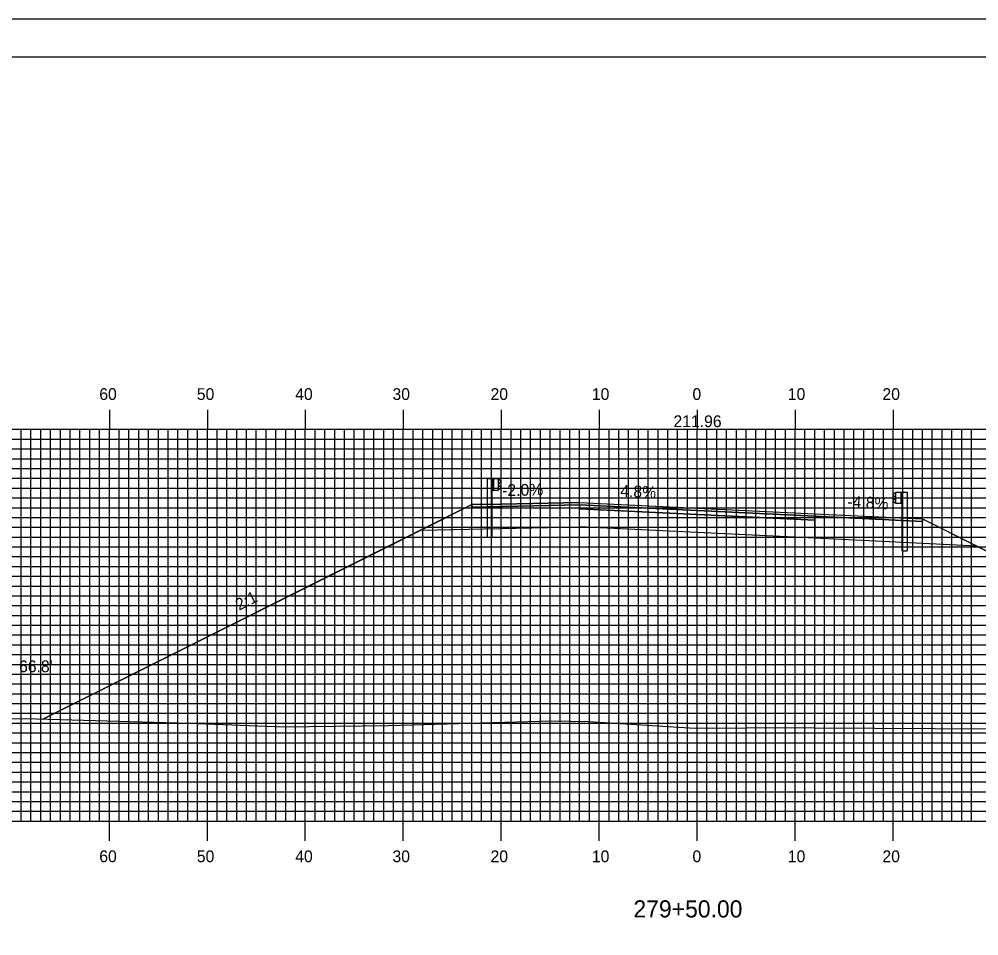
# Model space of a CAD drawing. Extents: x 1810587 to 1810930, y 442591 to 442811.
# Drawn here: x 1810683.2 to 1810781.1, y 442716.9 to 442810.5 of the extents above; entities that cross this region are included whole.
import ezdxf

# ---------------------------------------------------------------- set-up
doc = ezdxf.new("R2010")
doc.units = 0
for name, color, linetype in [('ANNOTATION', 7, 'Continuous'), ('BORDER', 7, 'Continuous'), ('D_Guardrail_Beam_Lt', 7, 'Continuous'), ('D_Guardrail_Beam_Rt', 7, 'Continuous'), ('D_Roadway_Centerline', 7, 'Continuous'), ('D_Roadway_Centerline_Text', 7, 'Continuous'), ('D_Roadway_Edge_Shoulder', 7, 'Continuous'), ('D_Roadway_Edge_TW', 7, 'Continuous'), ('D_Roadway_Pavement', 7, 'Continuous'), ('D_Roadway_SlopeLines', 7, 'Continuous'), ('D_Roadway_SubGrade', 7, 'Continuous'), ('D_Text_Standard', 7, 'Continuous'), ('H_V ANNOTATION', 7, 'Continuous'), ('MAJOR', 7, 'Continuous'), ('MINOR', 7, 'Continuous'), ('PLOT BOUNDARY', 7, 'Continuous'), ('S_Roadway_Centerline', 7, 'Continuous')]:
    doc.layers.add(name, color=color, linetype=linetype)

msp = doc.modelspace()

# ---------------------------------------------------------------- linework, layer by layer
at = {"layer": 'BORDER'}
msp.add_lwpolyline([(1810602.777, 442596.665), (1810922.777, 442596.665), (1810922.777, 442806.665), (1810602.777, 442806.665)], close=True, dxfattribs=at)
at = {"layer": 'D_Guardrail_Beam_Lt'}
for p, q in [((1810730.947, 442763.62), (1810730.947, 442757.62)), ((1810731.418, 442763.62), (1810730.947, 442763.62)), ((1810732.106, 442763.62), (1810731.418, 442763.62)), ((1810731.418, 442763.62), (1810731.418, 442762.453)), ((1810731.481, 442763.62), (1810731.481, 442762.453)), ((1810731.585, 442763.62), (1810731.585, 442762.453)), ((1810732.106, 442762.453), (1810732.106, 442763.62)), ((1810732.106, 442763.536), (1810732.18, 442763.522)), ((1810732.339, 442763.272), (1810732.144, 442763.136)), ((1810732.196, 442763.515), (1810732.339, 442763.415)), ((1810731.418, 442762.453), (1810732.106, 442762.453)), ((1810731.439, 442757.62), (1810731.439, 442762.453)), ((1810732.18, 442762.551), (1810732.106, 442762.536)), ((1810732.11, 442763.071), (1810732.11, 442763.001)), ((1810732.144, 442762.937), (1810732.339, 442762.801)), ((1810732.339, 442762.657), (1810732.196, 442762.557)), ((1810731.439, 442757.62), (1810730.947, 442757.62))]:
    msp.add_line(p, q, dxfattribs=at)
for centre, major_axis, start_param, end_param in [((1810732.189, 442763.071), (-0.0789, 0), 5.323254, 6.283185), ((1810732.172, 442763.481), (0.0417, 0), 0.959931, 1.376053), ((1810732.289, 442763.343), (0.0877, 0), 5.323254, 7.243116), ((1810732.189, 442763.001), (-0.0789, 0), 6.283185, 7.243116), ((1810732.172, 442762.591), (0.0417, 0), 4.907132, 5.323254), ((1810732.289, 442762.729), (0.0877, 0), 5.323254, 7.243116)]:
    msp.add_ellipse(centre, major_axis=major_axis, ratio=0.995501, start_param=start_param, end_param=end_param, dxfattribs=at)
at = {"layer": 'D_Guardrail_Beam_Rt'}
for p, q in [((1810772.647, 442762.16), (1810772.573, 442762.146)), ((1810772.647, 442762.244), (1810773.335, 442762.244)), ((1810772.647, 442761.077), (1810772.647, 442762.244)), ((1810773.168, 442762.244), (1810773.168, 442761.077)), ((1810773.272, 442762.244), (1810773.272, 442761.077)), ((1810773.335, 442762.244), (1810773.806, 442762.244)), ((1810773.335, 442762.244), (1810773.335, 442761.077)), ((1810773.806, 442762.244), (1810773.806, 442756.244)), ((1810772.557, 442762.139), (1810772.414, 442762.039)), ((1810772.414, 442761.896), (1810772.609, 442761.76)), ((1810772.609, 442761.561), (1810772.414, 442761.425)), ((1810772.414, 442761.281), (1810772.557, 442761.181)), ((1810772.573, 442761.175), (1810772.647, 442761.16)), ((1810772.643, 442761.695), (1810772.643, 442761.625)), ((1810773.335, 442761.077), (1810772.647, 442761.077)), ((1810773.314, 442756.244), (1810773.314, 442761.077)), ((1810773.314, 442756.244), (1810773.806, 442756.244))]:
    msp.add_line(p, q, dxfattribs=at)
for centre, major_axis, start_param, end_param in [((1810772.464, 442761.967), (-0.0877, 0), 5.323254, 7.243116), ((1810772.464, 442761.353), (-0.0877, 0), 5.323254, 7.243116), ((1810772.581, 442762.105), (-0.0417, 0), 4.907132, 5.323254), ((1810772.581, 442761.215), (-0.0417, 0), 0.959931, 1.376053), ((1810772.564, 442761.695), (0.0789, 0), 0, 0.959931), ((1810772.564, 442761.625), (0.0789, 0), 5.323254, 6.283185)]:
    msp.add_ellipse(centre, major_axis=major_axis, ratio=0.995501, start_param=start_param, end_param=end_param, dxfattribs=at)
at = {"layer": 'D_Roadway_Centerline'}
msp.add_lwpolyline([(1810685.574, 442739.075), (1810724.168, 442758.372), (1810729.377, 442760.976), (1810732.377, 442761.036), (1810740.377, 442761.196), (1810752.377, 442760.62), (1810764.377, 442760.044), (1810772.377, 442759.66), (1810775.377, 442759.516), (1810780.908, 442756.751), (1810818.962, 442737.723)], dxfattribs=at)
at = {"layer": 'D_Roadway_Edge_Shoulder'}
for points in [[(1810740.377, 442761.196), (1810732.377, 442761.036), (1810732.377, 442761.036), (1810729.377, 442760.976), (1810729.377, 442760.726), (1810740.377, 442760.946)], [(1810764.377, 442760.044), (1810772.377, 442759.66), (1810772.377, 442759.66), (1810775.377, 442759.516), (1810775.377, 442759.266), (1810764.377, 442759.794)]]:
    msp.add_lwpolyline(points, close=True, dxfattribs=at)
at = {"layer": 'D_Roadway_Edge_TW'}
msp.add_lwpolyline([(1810740.377, 442760.946), (1810740.377, 442761.196), (1810752.377, 442760.62), (1810764.377, 442760.044), (1810764.377, 442759.794), (1810752.377, 442760.37)], close=True, dxfattribs=at)
at = {"layer": 'D_Roadway_Pavement'}
msp.add_lwpolyline([(1810740.377, 442760.53), (1810740.377, 442760.946), (1810752.377, 442760.37), (1810764.377, 442759.794), (1810764.377, 442759.378), (1810752.377, 442759.954)], close=True, dxfattribs=at)
for points in [[(1810740.377, 442760.946), (1810740.377, 442760.53)], [(1810764.377, 442759.794), (1810764.377, 442759.378)]]:
    msp.add_lwpolyline(points, dxfattribs=at)
at = {"layer": 'D_Roadway_SlopeLines'}
for points in [[(1810729.377, 442760.976), (1810685.574, 442739.075)], [(1810775.377, 442759.516), (1810818.962, 442737.723)]]:
    msp.add_lwpolyline(points, dxfattribs=at)
at = {"layer": 'D_Roadway_SubGrade'}
for points in [[(1810740.377, 442760.53), (1810740.377, 442760.946), (1810729.377, 442760.726), (1810729.377, 442760.976), (1810724.168, 442758.372), (1810740.377, 442758.696)], [(1810740.377, 442758.696), (1810740.377, 442760.946), (1810740.377, 442760.53), (1810752.377, 442759.954), (1810764.377, 442759.378), (1810764.377, 442759.794), (1810764.377, 442757.544), (1810752.377, 442758.12)], [(1810764.377, 442759.378), (1810764.377, 442759.794), (1810775.377, 442759.266), (1810775.377, 442759.516), (1810780.908, 442756.751), (1810764.377, 442757.544)]]:
    msp.add_lwpolyline(points, close=True, dxfattribs=at)
at = {"layer": 'MAJOR'}
for p, q in [((1810692.377, 442770.669), (1810692.377, 442768.665)), ((1810702.377, 442770.669), (1810702.377, 442768.665)), ((1810712.377, 442770.669), (1810712.377, 442768.665)), ((1810722.377, 442770.669), (1810722.377, 442768.665)), ((1810732.377, 442770.669), (1810732.377, 442768.665)), ((1810742.377, 442770.669), (1810742.377, 442768.665)), ((1810752.377, 442770.669), (1810752.377, 442768.665)), ((1810762.377, 442770.669), (1810762.377, 442768.665)), ((1810772.377, 442770.669), (1810772.377, 442768.665)), ((1810612.377, 442768.665), (1810892.377, 442768.665)), ((1810612.377, 442768.665), (1810892.377, 442768.665)), ((1810692.377, 442728.665), (1810692.377, 442768.665)), ((1810702.377, 442728.665), (1810702.377, 442768.665)), ((1810712.377, 442728.665), (1810712.377, 442768.665)), ((1810722.377, 442728.665), (1810722.377, 442768.665)), ((1810732.377, 442728.665), (1810732.377, 442768.665)), ((1810742.377, 442728.665), (1810742.377, 442768.665)), ((1810752.377, 442728.665), (1810752.377, 442768.665)), ((1810762.377, 442728.665), (1810762.377, 442768.665)), ((1810772.377, 442728.665), (1810772.377, 442768.665)), ((1810612.377, 442763.665), (1810892.377, 442763.665)), ((1810612.377, 442758.665), (1810892.377, 442758.665)), ((1810612.377, 442753.665), (1810892.377, 442753.665)), ((1810612.377, 442748.665), (1810892.377, 442748.665)), ((1810612.377, 442743.665), (1810892.377, 442743.665)), ((1810612.377, 442738.665), (1810892.377, 442738.665)), ((1810612.377, 442733.665), (1810892.377, 442733.665)), ((1810612.377, 442728.665), (1810892.377, 442728.665)), ((1810612.377, 442728.665), (1810892.377, 442728.665)), ((1810692.377, 442726.661), (1810692.377, 442728.665)), ((1810702.377, 442726.661), (1810702.377, 442728.665)), ((1810712.377, 442726.661), (1810712.377, 442728.665)), ((1810722.377, 442726.661), (1810722.377, 442728.665)), ((1810732.377, 442726.661), (1810732.377, 442728.665)), ((1810742.377, 442726.661), (1810742.377, 442728.665)), ((1810752.377, 442726.661), (1810752.377, 442728.665)), ((1810762.377, 442726.661), (1810762.377, 442728.665)), ((1810772.377, 442726.661), (1810772.377, 442728.665))]:
    msp.add_line(p, q, dxfattribs=at)
at = {"layer": 'MINOR'}
for p, q in [((1810683.377, 442728.665), (1810683.377, 442768.665)), ((1810684.377, 442728.665), (1810684.377, 442768.665)), ((1810685.377, 442728.665), (1810685.377, 442768.665)), ((1810686.377, 442728.665), (1810686.377, 442768.665)), ((1810687.377, 442728.665), (1810687.377, 442768.665)), ((1810688.377, 442728.665), (1810688.377, 442768.665)), ((1810689.377, 442728.665), (1810689.377, 442768.665)), ((1810690.377, 442728.665), (1810690.377, 442768.665)), ((1810691.377, 442728.665), (1810691.377, 442768.665)), ((1810693.377, 442728.665), (1810693.377, 442768.665)), ((1810694.377, 442728.665), (1810694.377, 442768.665)), ((1810695.377, 442728.665), (1810695.377, 442768.665)), ((1810696.377, 442728.665), (1810696.377, 442768.665)), ((1810697.377, 442728.665), (1810697.377, 442768.665)), ((1810698.377, 442728.665), (1810698.377, 442768.665)), ((1810699.377, 442728.665), (1810699.377, 442768.665)), ((1810700.377, 442728.665), (1810700.377, 442768.665)), ((1810701.377, 442728.665), (1810701.377, 442768.665)), ((1810703.377, 442728.665), (1810703.377, 442768.665)), ((1810704.377, 442728.665), (1810704.377, 442768.665)), ((1810705.377, 442728.665), (1810705.377, 442768.665)), ((1810706.377, 442728.665), (1810706.377, 442768.665)), ((1810707.377, 442728.665), (1810707.377, 442768.665)), ((1810708.377, 442728.665), (1810708.377, 442768.665)), ((1810709.377, 442728.665), (1810709.377, 442768.665)), ((1810710.377, 442728.665), (1810710.377, 442768.665)), ((1810711.377, 442728.665), (1810711.377, 442768.665)), ((1810713.377, 442728.665), (1810713.377, 442768.665)), ((1810714.377, 442728.665), (1810714.377, 442768.665)), ((1810715.377, 442728.665), (1810715.377, 442768.665)), ((1810716.377, 442728.665), (1810716.377, 442768.665)), ((1810717.377, 442728.665), (1810717.377, 442768.665)), ((1810718.377, 442728.665), (1810718.377, 442768.665)), ((1810719.377, 442728.665), (1810719.377, 442768.665)), ((1810720.377, 442728.665), (1810720.377, 442768.665)), ((1810721.377, 442728.665), (1810721.377, 442768.665)), ((1810723.377, 442728.665), (1810723.377, 442768.665)), ((1810724.377, 442728.665), (1810724.377, 442768.665)), ((1810725.377, 442728.665), (1810725.377, 442768.665)), ((1810726.377, 442728.665), (1810726.377, 442768.665)), ((1810727.377, 442728.665), (1810727.377, 442768.665)), ((1810728.377, 442728.665), (1810728.377, 442768.665)), ((1810729.377, 442728.665), (1810729.377, 442768.665)), ((1810730.377, 442728.665), (1810730.377, 442768.665)), ((1810731.377, 442728.665), (1810731.377, 442768.665)), ((1810733.377, 442728.665), (1810733.377, 442768.665)), ((1810734.377, 442728.665), (1810734.377, 442768.665)), ((1810735.377, 442728.665), (1810735.377, 442768.665)), ((1810736.377, 442728.665), (1810736.377, 442768.665)), ((1810737.377, 442728.665), (1810737.377, 442768.665)), ((1810738.377, 442728.665), (1810738.377, 442768.665)), ((1810739.377, 442728.665), (1810739.377, 442768.665)), ((1810740.377, 442728.665), (1810740.377, 442768.665)), ((1810741.377, 442728.665), (1810741.377, 442768.665)), ((1810743.377, 442728.665), (1810743.377, 442768.665)), ((1810744.377, 442728.665), (1810744.377, 442768.665)), ((1810745.377, 442728.665), (1810745.377, 442768.665)), ((1810746.377, 442728.665), (1810746.377, 442768.665)), ((1810747.377, 442728.665), (1810747.377, 442768.665)), ((1810748.377, 442728.665), (1810748.377, 442768.665)), ((1810749.377, 442728.665), (1810749.377, 442768.665)), ((1810750.377, 442728.665), (1810750.377, 442768.665)), ((1810751.377, 442728.665), (1810751.377, 442768.665)), ((1810753.377, 442728.665), (1810753.377, 442768.665)), ((1810754.377, 442728.665), (1810754.377, 442768.665)), ((1810755.377, 442728.665), (1810755.377, 442768.665)), ((1810756.377, 442728.665), (1810756.377, 442768.665)), ((1810757.377, 442728.665), (1810757.377, 442768.665)), ((1810758.377, 442728.665), (1810758.377, 442768.665)), ((1810759.377, 442728.665), (1810759.377, 442768.665)), ((1810760.377, 442728.665), (1810760.377, 442768.665)), ((1810761.377, 442728.665), (1810761.377, 442768.665)), ((1810763.377, 442728.665), (1810763.377, 442768.665)), ((1810764.377, 442728.665), (1810764.377, 442768.665)), ((1810765.377, 442728.665), (1810765.377, 442768.665)), ((1810766.377, 442728.665), (1810766.377, 442768.665)), ((1810767.377, 442728.665), (1810767.377, 442768.665)), ((1810768.377, 442728.665), (1810768.377, 442768.665)), ((1810769.377, 442728.665), (1810769.377, 442768.665)), ((1810770.377, 442728.665), (1810770.377, 442768.665)), ((1810771.377, 442728.665), (1810771.377, 442768.665)), ((1810773.377, 442728.665), (1810773.377, 442768.665)), ((1810774.377, 442728.665), (1810774.377, 442768.665)), ((1810775.377, 442728.665), (1810775.377, 442768.665)), ((1810776.377, 442728.665), (1810776.377, 442768.665)), ((1810777.377, 442728.665), (1810777.377, 442768.665)), ((1810778.377, 442728.665), (1810778.377, 442768.665)), ((1810779.377, 442728.665), (1810779.377, 442768.665)), ((1810780.377, 442728.665), (1810780.377, 442768.665)), ((1810612.377, 442767.665), (1810892.377, 442767.665)), ((1810612.377, 442766.665), (1810892.377, 442766.665)), ((1810612.377, 442765.665), (1810892.377, 442765.665)), ((1810612.377, 442764.665), (1810892.377, 442764.665)), ((1810612.377, 442762.665), (1810892.377, 442762.665)), ((1810612.377, 442761.665), (1810892.377, 442761.665)), ((1810612.377, 442760.665), (1810892.377, 442760.665)), ((1810612.377, 442759.665), (1810892.377, 442759.665)), ((1810612.377, 442757.665), (1810892.377, 442757.665)), ((1810612.377, 442756.665), (1810892.377, 442756.665)), ((1810612.377, 442755.665), (1810892.377, 442755.665)), ((1810612.377, 442754.665), (1810892.377, 442754.665)), ((1810612.377, 442752.665), (1810892.377, 442752.665)), ((1810612.377, 442751.665), (1810892.377, 442751.665)), ((1810612.377, 442750.665), (1810892.377, 442750.665)), ((1810612.377, 442749.665), (1810892.377, 442749.665)), ((1810612.377, 442747.665), (1810892.377, 442747.665)), ((1810612.377, 442746.665), (1810892.377, 442746.665)), ((1810612.377, 442745.665), (1810892.377, 442745.665)), ((1810612.377, 442744.665), (1810892.377, 442744.665)), ((1810612.377, 442742.665), (1810892.377, 442742.665)), ((1810612.377, 442741.665), (1810892.377, 442741.665)), ((1810612.377, 442740.665), (1810892.377, 442740.665)), ((1810612.377, 442739.665), (1810892.377, 442739.665)), ((1810612.377, 442737.665), (1810892.377, 442737.665)), ((1810612.377, 442736.665), (1810892.377, 442736.665)), ((1810612.377, 442735.665), (1810892.377, 442735.665)), ((1810612.377, 442734.665), (1810892.377, 442734.665)), ((1810612.377, 442732.665), (1810892.377, 442732.665)), ((1810612.377, 442731.665), (1810892.377, 442731.665)), ((1810612.377, 442730.665), (1810892.377, 442730.665)), ((1810612.377, 442729.665), (1810892.377, 442729.665))]:
    msp.add_line(p, q, dxfattribs=at)
at = {"layer": 'PLOT BOUNDARY'}
msp.add_lwpolyline([(1810586.59, 442590.547), (1810926.59, 442590.547), (1810926.59, 442810.547), (1810586.59, 442810.547)], close=True, dxfattribs=at)
at = {"layer": 'S_Roadway_Centerline'}
msp.add_lwpolyline([(1810612.377, 442740.403), (1810617.462, 442740.055), (1810622.558, 442739.785), (1810628.316, 442739.724), (1810638.526, 442739.577), (1810656.386, 442739.297), (1810658.007, 442739.312), (1810659.285, 442739.228), (1810670.597, 442738.88), (1810683.757, 442739.125), (1810700.479, 442738.664), (1810710.156, 442738.284), (1810720.854, 442738.411), (1810737.474, 442738.884), (1810739.437, 442738.87), (1810741.277, 442738.823), (1810752.122, 442738.14), (1810762.757, 442738.223), (1810764.361, 442738.195), (1810782.794, 442738.075)], dxfattribs=at)

# ---------------------------------------------------------------- texts
at = {"layer": 'ANNOTATION'}
for s, rotation, p in [('-2.0%', 1.14576, (1810732.483, 442761.839)), ('4.8%', 357.25191, (1810744.506, 442761.8)), ('-4.8%', 357.25191, (1810767.685, 442760.688)), ('2:1', 26.56505, (1810705.62, 442750.134))]:
    msp.add_text(s, height=1.2, rotation=rotation, dxfattribs=at).set_placement(p)
at = {"layer": 'D_Roadway_Centerline'}
for s, p in [('C', (1810752.371, 442760.62)), ('L', (1810752.377, 442760.613))]:
    msp.add_text(s, height=0.0146, dxfattribs=at).set_placement(p)
at = {"layer": 'D_Roadway_Centerline_Text'}
msp.add_text('211.96', height=1.2, dxfattribs=at).set_placement((1810749.958, 442768.891))
at = {"layer": 'D_Text_Standard'}
msp.add_text("66.8'", height=1.2, dxfattribs=at).set_placement((1810683.161, 442743.863))
at = {"layer": 'H_V ANNOTATION'}
for s, height, p in [('60', 1.2, (1810691.349, 442771.665)), ('50', 1.2, (1810701.306, 442771.665)), ('40', 1.2, (1810711.349, 442771.665)), ('30', 1.2, (1810721.274, 442771.665)), ('20', 1.2, (1810731.285, 442771.665)), ('10', 1.2, (1810741.627, 442771.665)), ('0', 1.2, (1810751.895, 442771.665)), ('10', 1.2, (1810761.627, 442771.665)), ('20', 1.2, (1810771.285, 442771.665)), ('60', 1.2, (1810691.349, 442724.465)), ('50', 1.2, (1810701.306, 442724.465)), ('40', 1.2, (1810711.349, 442724.465)), ('30', 1.2, (1810721.274, 442724.465)), ('20', 1.2, (1810731.285, 442724.465)), ('10', 1.2, (1810741.627, 442724.465)), ('0', 1.2, (1810751.895, 442724.465)), ('10', 1.2, (1810761.627, 442724.465)), ('20', 1.2, (1810771.285, 442724.465)), ('279+50.00', 1.75, (1810745.868, 442718.821))]:
    msp.add_text(s, height=height, dxfattribs=at).set_placement(p)

doc.saveas('drawing.dxf')
